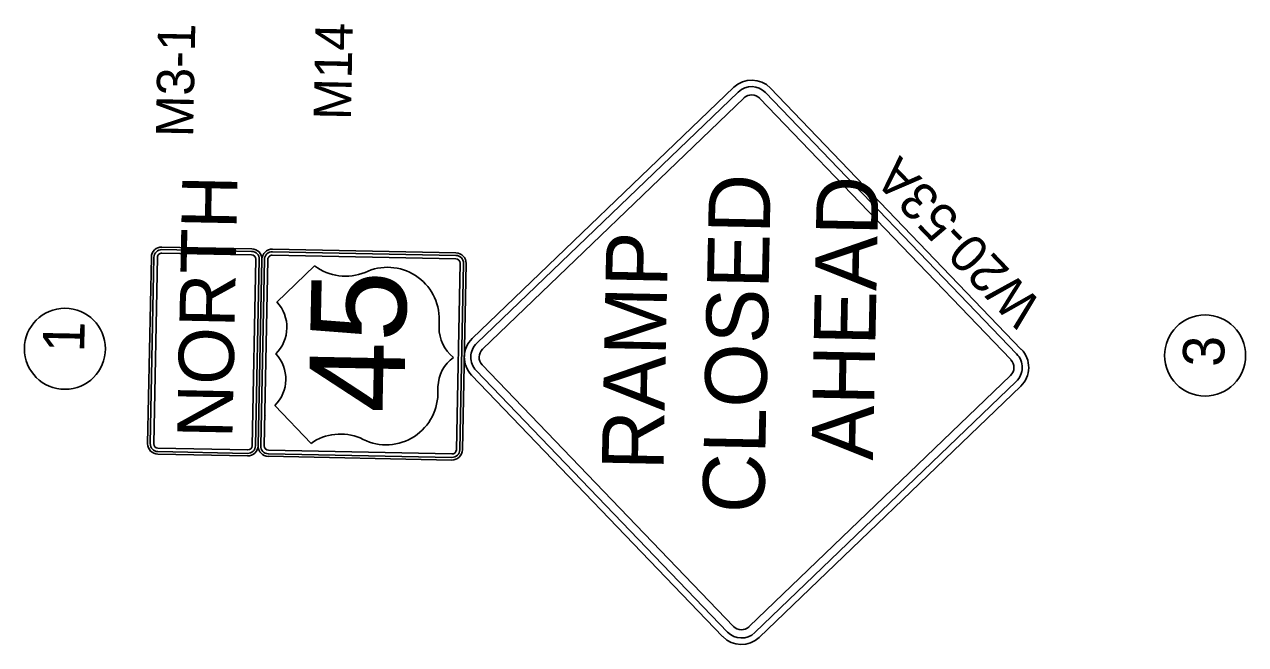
# Model space of a CAD drawing. Extents: x 331323 to 388339, y 121519 to 205315.
# Drawn here: x 363503 to 365624, y 139013 to 140090 of the extents above; entities that cross this region are included whole.
import ezdxf

# ---------------------------------------------------------------- set-up
doc = ezdxf.new("R2010")
doc.units = 0
doc.layers.add('CA-TEXT', color=7, linetype='Continuous')
doc.layers.add('P_SGN_Cell', color=7, linetype='Continuous')

msp = doc.modelspace()

# ---------------------------------------------------------------- linework, layer by layer
at = {"layer": 'CA-TEXT'}
for centre in [(363573, 139526.7), (365553.9, 139515)]:
    msp.add_circle(centre, 70.4, dxfattribs=at)
at = {"layer": 'P_SGN_Cell'}
for p, q in [((363741.3, 139693), (363897.3, 139689.9)), ((363741.5, 139703.5), (363897.5, 139700.4)), ((363741.5, 139699), (363897.4, 139695.9)), ((363933.3, 139689.3), (364252.2, 139682.9)), ((363933.4, 139695.3), (364252.3, 139688.9)), ((363933.5, 139699.8), (364252.4, 139693.4)), ((363716.7, 139361.7), (363723.2, 139685.9)), ((363721.2, 139361.9), (363727.7, 139685.8)), ((363727.2, 139361.7), (363733.7, 139685.7)), ((363904.7, 139682.2), (363898.1, 139358.3)), ((363910.6, 139682.1), (363904.1, 139358.2)), ((363908.6, 139358), (363915.2, 139682.1)), ((363915.1, 139682), (363908.6, 139358.1)), ((363913.1, 139358.1), (363919.7, 139682.1)), ((363919.1, 139358), (363925.6, 139681.9)), ((363941.1, 139607.9), (364006.7, 139670.9)), ((364259.5, 139675.2), (364253, 139351.3)), ((364265.5, 139675.1), (364259, 139351.2)), ((364270, 139675), (364263.5, 139351.1)), ((364223.4, 139576.5), (364223.2, 139563.7)), ((364221.1, 139460.8), (364220.9, 139448)), ((364000.5, 139362.4), (363937.5, 139428)), ((363922.3, 139410.2), (363922.3, 139410.2)), ((363734.5, 139354.1), (363890.5, 139351)), ((363926.5, 139350.4), (364245.4, 139343.9)), ((363734.3, 139343.6), (363890.3, 139340.5)), ((363734.4, 139348.1), (363890.4, 139345)), ((363926.3, 139339.9), (364245.1, 139333.4)), ((363926.4, 139344.4), (364245.2, 139337.9))]:
    msp.add_line(p, q, dxfattribs=at)
for points in [[(364735, 139981), (364280.6, 139544.6)], [(364742.9, 139972.8), (364288.5, 139536.3)], [(365226.4, 139517.8), (364790.1, 139972)], [(365234.6, 139525.7), (364798.4, 139979.9)], [(364752.8, 139962.5), (364298.4, 139526)], [(365216.1, 139507.9), (364779.8, 139962.1)], [(364297.9, 139498.8), (364734.3, 139044.4)], [(364279.3, 139481), (364715.7, 139026.6)], [(364287.6, 139488.9), (364724, 139034.5)], [(364761.5, 139043.9), (365215.9, 139480.3)], [(364771.4, 139033.6), (365225.8, 139470)], [(364779.4, 139025.3), (365233.7, 139461.7)]]:
    msp.add_lwpolyline(points, dxfattribs=at)
for centre, radius, start, end in [((364766.1, 139948.5), 45, 43.8462, 133.8462), ((364766.1, 139948.5), 33.6, 43.8462, 133.8462), ((364766.1, 139948.5), 19.3, 43.8462, 133.8462), ((363741.2, 139685.5), 18, 88.8462, 178.8462), ((363741.2, 139685.5), 13.5, 88.8462, 178.8462), ((363741.2, 139685.5), 7.5, 88.8462, 178.8462), ((363897.2, 139682.4), 7.5, 358.8462, 88.8462), ((363897.2, 139682.4), 13.5, 358.8462, 88.8462), ((363897.2, 139682.4), 18, 358.8462, 88.8462), ((363933.1, 139681.8), 18, 88.8462, 178.8462), ((363933.1, 139681.8), 13.5, 88.8462, 178.8462), ((363933.1, 139681.8), 7.5, 88.8462, 178.8462), ((364252, 139675.4), 18, 358.8462, 88.8462), ((364060.7, 139742.9), 90, 233.1143, 291.9873), ((364133.4, 139578.3), 90, 358.8462, 115.6928), ((364252, 139675.4), 7.5, 358.8462, 88.8462), ((364252, 139675.4), 13.5, 358.8462, 88.8462), ((363894.3, 139563.9), 64.3, 314.4191, 43.2734), ((364288.2, 139562.8), 65.1, 179.1885, 231.634), ((364311.8, 139512.1), 45, 133.8443, 223.8462), ((364311.8, 139512.1), 33.6, 133.8443, 223.8462), ((364311.8, 139512.1), 19.3, 133.8443, 223.8462), ((365202.5, 139494.2), 45, 313.8534, 44.4971), ((363892.5, 139473.9), 64.3, 314.4191, 43.2734), ((364286.2, 139459.1), 65.1, 126.0584, 178.5039), ((365202.5, 139494.2), 19.3, 313.8534, 44.4971), ((365202.5, 139494.2), 33.6, 313.8534, 44.4971), ((364130.9, 139449.8), 90, 240.0981, 358.8463), ((364051.9, 139288.5), 90, 67.7159, 124.7982), ((363734.7, 139361.6), 18, 179.6119, 268.8462), ((363734.7, 139361.6), 13.5, 178.8462, 268.8462), ((363734.7, 139361.6), 7.5, 178.8462, 268.8462), ((363890.6, 139358.5), 18, 268.8462, 358.8462), ((363890.6, 139358.5), 13.5, 268.8462, 358.8462), ((363890.6, 139358.5), 7.5, 268.8462, 358.8462), ((363926.6, 139357.8), 18, 179.6119, 268.8462), ((363926.6, 139357.8), 13.5, 178.8462, 268.8462), ((363926.6, 139357.8), 7.5, 178.8462, 268.8462), ((364245.5, 139351.4), 18, 268.8462, 358.8462), ((364245.5, 139351.4), 13.5, 268.8462, 358.8462), ((364245.5, 139351.4), 7.5, 268.8462, 358.8462), ((364748.2, 139057.8), 33.6, 223.8462, 313.8462), ((364748.2, 139057.8), 19.3, 223.8462, 313.8462), ((364748.2, 139057.8), 45, 223.8462, 313.8462)]:
    msp.add_arc(centre, radius, start, end, dxfattribs=at)

# ---------------------------------------------------------------- texts
at = {"layer": 'CA-TEXT'}
for s, p in [('1', (363606.4, 139520)), ('3', (365586.9, 139495))]:
    msp.add_text(s, height=72, rotation=88.8468, dxfattribs=at).set_placement(p)
at = {"layer": 'P_SGN_Cell'}
for s, height, rotation, p in [('M3-1', 64.8, 88.8462, (363795.6, 139894)), ('M14', 64.8, 88.8462, (364069.7, 139923.8)), ('W20-53A', 64.8, 133.8468, (365273.5, 139603.4)), ('NORTH', 96, 88.8462, (363863.8, 139370.7)), ('CLOSED', 107.14, 88.8462, (364787.7, 139240.3)), ('AHEAD', 107.14, 88.8462, (364976.9, 139332.4)), ('RAMP', 107.14, 88.8462, (364612.7, 139315)), ('45', 165.6, 88.8462, (364162.1, 139414.4))]:
    msp.add_text(s, height=height, rotation=rotation, dxfattribs=at).set_placement(p)

doc.saveas('drawing.dxf')
